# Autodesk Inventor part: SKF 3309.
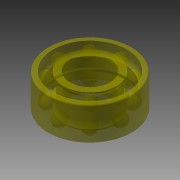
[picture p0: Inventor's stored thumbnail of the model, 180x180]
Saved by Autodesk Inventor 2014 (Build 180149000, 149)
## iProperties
Shininess: 20.0
Length Units: 11269
Angle Units: 11279
Time Units: 11290
Mass Units: 11283
Length Display Precision: 3
Angle Display Precision: 2
Created: 2001-02
Part Number: SKF 3309.
Material: Steel, Mild
Description: Bearing SKF 3309.
Document SubType Name: Modeling
Density: 7.86 g/cm^3
Appearance: Yellow(Clear)
ProtocolID: P00020917111527967
Protocol: P00020917111527967<@PID>[Version]<@EL>Version=2.2<@EL>[Calc]<@EL>WizardMode=2<@EL>ScnVisible=0<@EL>Bmax=<@EL>Bmin=<@EL>Dmax=45<@EL>Dmin=45<@EL>DDmax=<@EL>DDmin=
Control State: 0
Master: False
Checked Out: False
BOM1: Bearing
BOM2: SKF 3309
Density: 7.86
Volumn: 5.508610385591562
Area: 53.24970126743953
PropertySet Name: Model Information
Author: PaulN
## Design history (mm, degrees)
node "WorkPlane2"
node "WorkPlane4"
workplane "Work Plane3"
node "WorkPlane6"
node "Sketch1"
node "WorkPoint1"
node "WorkPlane3"
node "WorkPlane5"
extrude "ExtrusionBlind1" new body distance "d3" = 39.7 (= prf_b); taper "d4" = 0 deg
  node "Sketch2" dims "d2" = 100 (= prf_dd)
node "Sketch3"
node "WorkPoint2"
node "WorkAxis1"
sketch "Sketch4"
  geometry: C1 r 50 at (0, 0) reference
hole "Hole1" sketch "Sketch4" diameter "d6" = 45 (= prf_d); stored, may be unused: countersink angle "d10" = 60 deg, drill point angle "d12" = 118 deg; dims "d7" = 6, "d8" = 4, "d9" = 2, "d11" = 8
sketch "Sketch5"
  geometry: L1 (43.95, 39.7)-(43.95, 32); L2 (31.63, 39.7)-(43.95, 39.7); L3 (31.63, 38.16)-(31.63, 39.7); L4 (28.55, 7.7)-(28.55, 32); L5 (31.63, 0)-(31.63, 1.54); L6 (43.95, 0)-(31.63, 0); L7 (43.95, 7.7)-(43.95, 0); L8 (40.87, 25.84)-(40.87, 13.86); L9 (-50, 39.7)-(50, 39.7) reference; L10 (-50, 0)-(50, 0) reference; L11 (0, 29.338)-(0, -15.338); L12 (0, -26.346)-(0, 50.708) reference; A1 r 7.7 centre (36.25, 32) between (40.87, 25.84) and (43.95, 32); A2 r 7.7 centre (36.25, 32) between (31.63, 38.16) and (28.55, 32); A3 r 7.7 centre (36.25, 7.7) between (28.55, 7.7) and (31.63, 1.54); A4 r 7.7 centre (36.25, 7.7) between (43.95, 7.7) and (40.87, 13.86)
  constraints: 18 end point, 8 point on circle, 6 vertical, 5 collinear, 4 centre point, 4 tangent, 2 concentric, 2 equal radius, 2 horizontal
  dimensions: "d14" = 7.7 horizontal distance of A2.centre L1.start (= 0.5 x msp_dd0); "d16" = 7.7 horizontal distance of A4.centre L6.start (= 0.5 x msp_dd0); "d18" = 7.7 radius of A1 (= 0.5 x msp_dd0); "d33" = 72.5 diameter of A2.centre L11 (= msp_mdtds); "d34" = 63.26 diameter of L3.start L11 (= msp_dd2); "d35" = 81.74 diameter of L8 L11 (= msp_vd2)
revolve "RevolutionFull1" sketch "Sketch5" stored, may be unused: angle "d19" = 360 deg
sketch "Sketch6"
  geometry: L1 (36.25, 15.4)-(36.25, 0); L2 (-50, 0)-(50, 0) reference; L3 (-43.95, 39.7)-(43.95, 39.7) reference; L4 (36.25, 15.4)-(36.25, 0); A1 r 7.7 centre (36.25, 7.7) between (36.25, 15.4) and (36.25, 0); A2 r 7.7 centre (36.25, 7.7) between (28.55, 7.7) and (31.63, 1.54) reference
  constraints: 4 end point, 2 point on circle, 1 centre point, 1 concentric, 1 midpoint, 1 vertical
  dimensions: "d21" = 7.7 radius of A1 (= 0.5 x msp_dd0)
revolve "RevolutionFull2" sketch "Sketch6" stored, may be unused: angle "d22" = 360 deg
pattern_circular "PolarArray1" dims angle "d25" = 360 deg
sketch "Sketch7"
  geometry: L1 (36.25, 39.7)-(36.25, 24.3); L2 (-43.95, 39.7)-(43.95, 39.7) reference; L3 (22.5, 0)-(-22.5, 0) reference; L4 (36.25, 39.7)-(36.25, 24.3); A1 r 7.7 centre (36.25, 32) between (36.25, 39.7) and (36.25, 24.3); A2 r 7.7 centre (36.25, 32) between (31.63, 38.16) and (28.55, 32) reference
  constraints: 4 end point, 2 point on circle, 1 centre point, 1 concentric, 1 midpoint, 1 vertical
  dimensions: "d27" = 7.7 radius of A1 (= 0.5 x msp_dd0)
revolve "RevolutionFull3" sketch "Sketch7" stored, may be unused: angle "d28" = 360 deg
pattern_circular "PolarArray2" dims angle "d31" = 360 deg
fillet "Fillet1" dims "d32" = 1.5 (= prf_r)
body "Solid1"
other parameters: "prf_d" = 45 [user parameter; used in 3 equation terms], "prf_b" = 39.7 [user parameter; used in 2 equation terms], "prf_r" = 1.5 [user parameter; used in 1 equation term], "msp_mdtds" = 72.5 (= 0.5 x prf_d + 0.5 x prf_dd) [user parameter; used in 4 equation terms], "msp_dd0" = 15.4 (= -0.28 x prf_d + 0.28 x prf_dd) [user parameter; used in 8 equation terms], "msp_dd2" = 63.26 (= msp_mdtds - 0.6 x msp_dd0) [user parameter; used in 1 equation term], "msp_ang" = 0 [user parameter], "msp_vd2" = 81.74 (= msp_mdtds + 0.6 x msp_dd0) [user parameter; used in 1 equation term], "d0" = -39.7 (computed from prf_b), "d5" = 0, "d13" = 2.8 (derived), "d15" = 2.8 (derived), "d17" = 2.8 (derived), "d20" = 2.8 (derived), "d26" = 2.8 (derived), "d37" = 0
